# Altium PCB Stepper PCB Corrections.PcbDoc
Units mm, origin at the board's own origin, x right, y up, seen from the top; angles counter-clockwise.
Board outline 195.58 x 105.66 mm, 2 copper layers (Top Layer, Bottom Layer); 57 components, 50 nets, 280 pads, 5 vias.
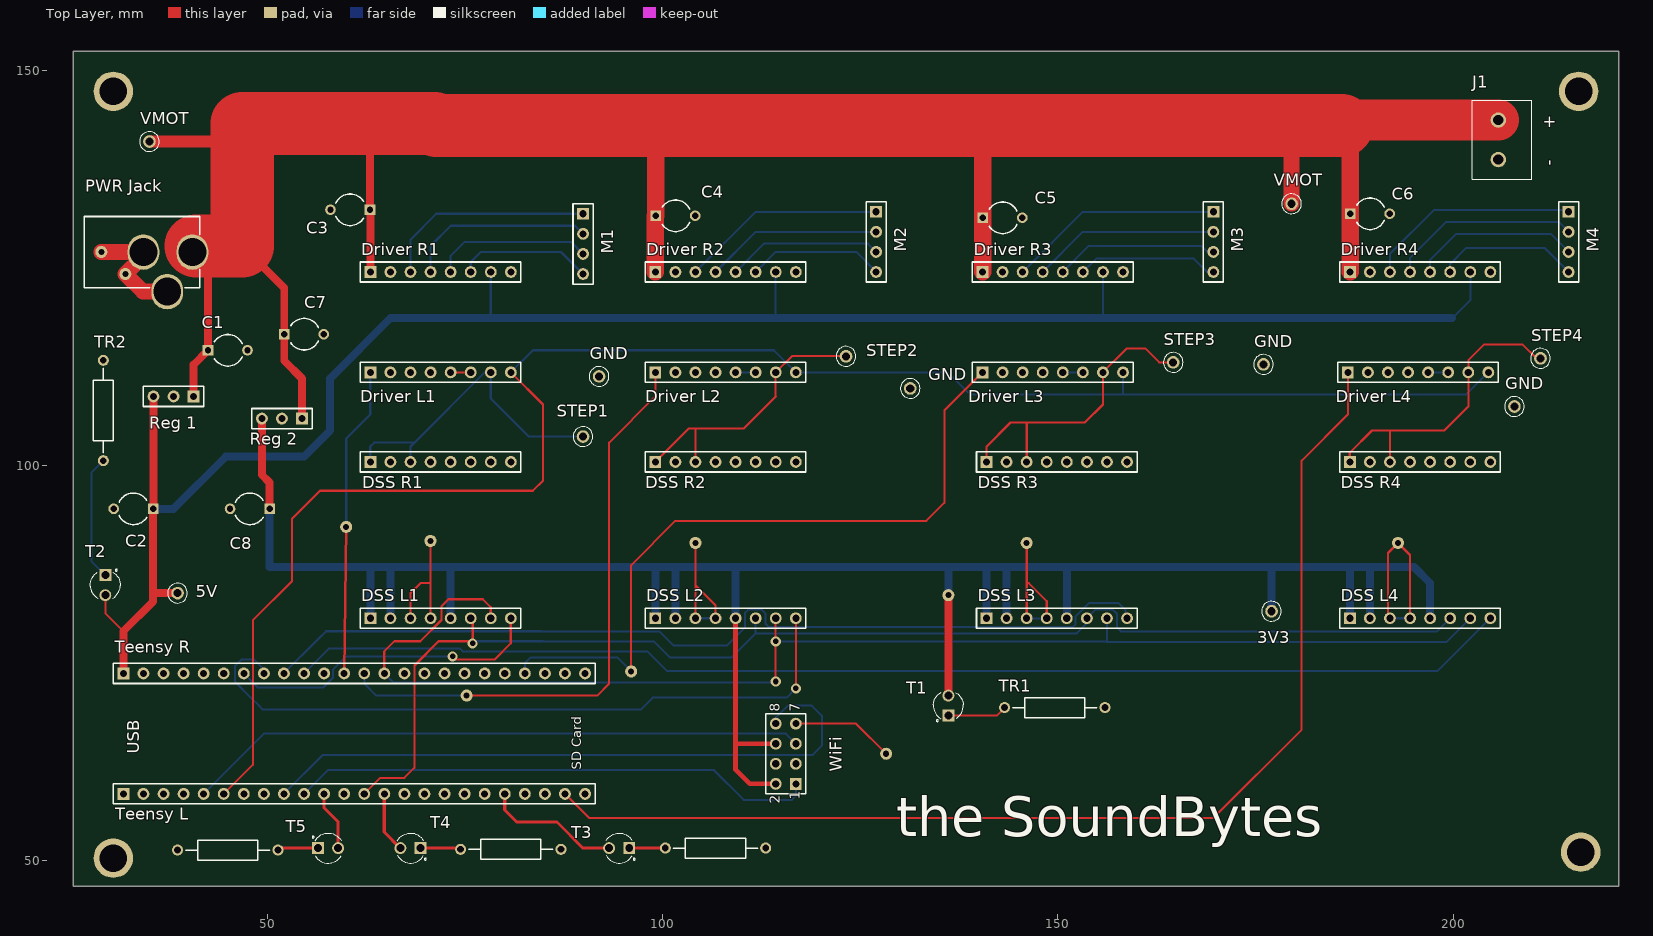
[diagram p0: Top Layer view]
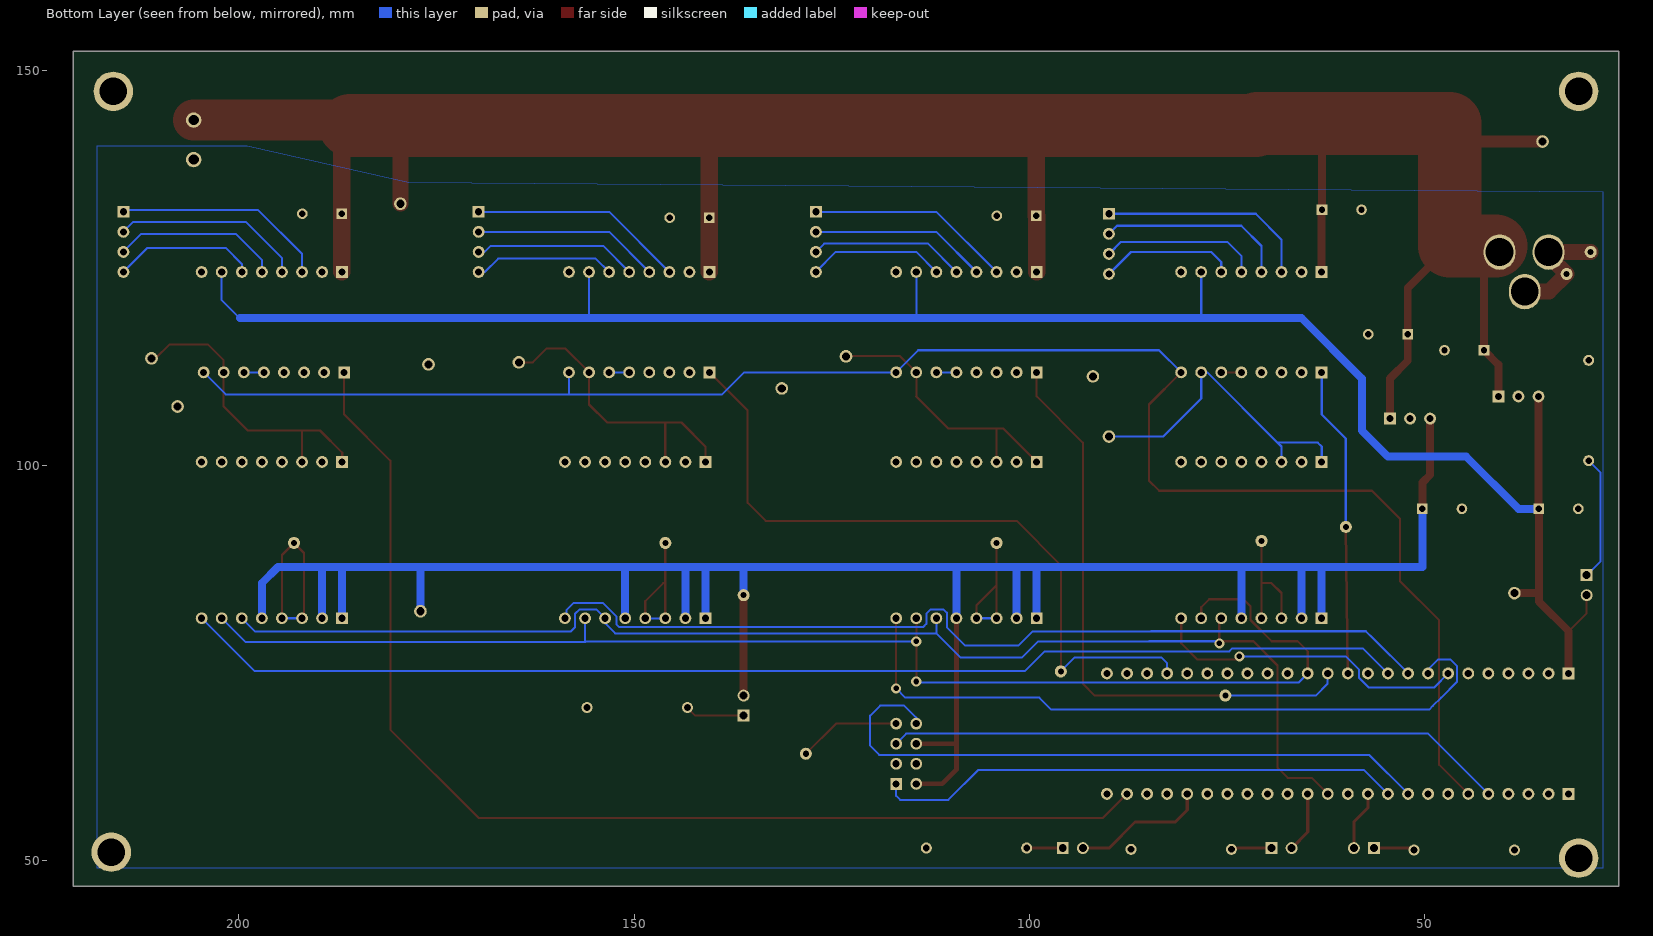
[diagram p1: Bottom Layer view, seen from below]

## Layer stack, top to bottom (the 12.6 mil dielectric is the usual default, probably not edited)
Top Solder: solder mask 0.0102, Solder Resist, Dk 3.5
Top Layer: signal copper 0.0356
Dielectric 1: dielectric 0.32, FR-4, Dk 4.8
Bottom Layer: signal copper 0.0356
Bottom Solder: solder mask 0.0102, Solder Resist, Dk 3.5

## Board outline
25.4,46.736 220.98,46.736 220.98,152.4 25.4,152.4

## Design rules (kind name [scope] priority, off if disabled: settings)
Clearance [All] p1: gap=0.254
PolygonConnect [All] p1: connectstyle=Relief reliefconductorwidth=0.254 reliefentries=4 polygonreliefangle="90 Angle" airgapwidth=0.254
RoutingVias [All] p1: holewidth=0.711 width=1.27 viastyle="Through Hole" minholewidth=0.711 minwidth=1.27 maxholewidth=0.711 maxwidth=1.27
SolderMaskExpansion [All] p1: expansion=0.102
Width Width_1 [All] p1: maxlimit=1 minlimit=0.28 preferedwidth=1 minimp=50.000000 maximp=50.000000 favimp=50.000000
Width [InNet('VMOT')] p2: maxlimit=8.2 minlimit=7.6 preferedwidth=8 minimp=50.000000 maximp=50.000000 favimp=50.000000
30 further rules are at their usual default settings.

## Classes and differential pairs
component class "Stepper Teensy Breakout": 3V3 5V C1 C2 C3 C4 C5 C6 C7 C8 "Driver L1" "Driver L2" "Driver L3" "Driver L4" "Driver R1" "Driver R2" "Driver R3" "Driver R4" "DSS L1" "DSS L2" "DSS L3" "DSS L4" "DSS R1" "DSS R2" "DSS R3" "DSS R4" GND J1 M1 M2 M3 M4 "PWR Jack" "Reg 1" "Reg 2" STEP1 STEP2 STEP3 STEP4 T1 T2 T3 T4 T5 "Teensy L" "Teensy R" TR1 TR2 VMOT WiFi

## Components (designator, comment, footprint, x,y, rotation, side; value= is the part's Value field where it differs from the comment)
3V3 "" TPCW51D250H460P 177.038,81.534 r0 top (schematic designator TP11)
5V "" TPCW51D250H460P 38.608,83.82 r90 top (schematic designator TP10)
C1 "Cap2" CAPR5-4X5 44.958,114.554 r0 top
C2 "Cap2" CAPR5-4X5 33.02,94.488 r180 top
C3 "" CAPR5-4X5 60.452,132.334 r180 top
C4 "Cap2" CAPR5-4X5 101.6,131.572 r0 top
C5 "Cap2" CAPR5-4X5 143.002,131.318 r0 top
C6 "Cap2" CAPR5-4X5 189.484,131.826 r0 top
C7 "Cap2" CAPR5-4X5 54.61,116.586 r0 top
C8 "Cap2" CAPR5-4X5 47.752,94.488 r180 top
"Driver L1" "Header 8" HDR1X8 63,111.76 r0 top
"Driver L2" "Header 8" HDR1X8 99.06,111.76 r0 top locked
"Driver L3" "Header 8" HDR1X8 140.462,111.76 r0 top locked
"Driver L4" "Header 8" HDR1X8 186.69,111.76 r0 top locked
"Driver R1" "Header 8" HDR1X8 63,124.46 r0 top
"Driver R2" "Header 8" HDR1X8 99.06,124.46 r0 top locked
"Driver R3" "Header 8" HDR1X8 140.462,124.46 r0 top locked
"Driver R4" "Header 8" HDR1X8 186.944,124.46 r0 top locked
"DSS L1" "Header 8" HDR1X8 63,80.645 r0 top locked
"DSS L2" "Header 8" HDR1X8 99.06,80.645 r0 top
"DSS L3" "Header 8" HDR1X8 140.97,80.645 r0 top locked
"DSS L4" "Header 8" HDR1X8 186.944,80.645 r0 top
"DSS R1" "Header 8" HDR1X8 63,100.42 r0 top locked
"DSS R2" "Header 8" HDR1X8 99.06,100.42 r0 top
"DSS R3" "Header 8" HDR1X8 140.97,100.42 r0 top
"DSS R4" "Header 8" HDR1X8 186.944,100.42 r0 top
GND "" TPCW51D250H460P 207.772,107.442 r0 top (schematic designator TP8)
GND "" TPCW51D250H460P 91.948,111.252 r0 top (schematic designator TP7)
GND "" TPCW51D250H460P 176.022,112.776 r0 top (schematic designator TP6)
GND "" TPCW51D250H460P 131.318,109.728 r0 top (schematic designator TP5)
J1 "" 691102710002 205.74,141.184 r270 top
M1 "Header 4" HDR1X4 89.916,131.826 r270 top (schematic designator "Motor 1")
M2 "Header 4" HDR1X4 127,132.08 r270 top (schematic designator "Motor 2")
M3 "Header 4" HDR1X4 169.672,132.08 r270 top (schematic designator "Motor 3")
M4 "Header 4" HDR1X4 214.63,132.08 r270 top (schematic designator "Motor 4")
"PWR Jack" "PWR2.5" KLD-0202 26.79,126.984 r0 top
"Reg 1" "Header 3" HDR1X3 40.64,108.712 r180 top (schematic designator "Sw Reg")
"Reg 2" "Header 2" HDR1X3 54.356,105.918 r180 top (schematic designator "Sw Reg1")
STEP1 "" TPCW51D250H460P 89.916,103.632 r0 top (schematic designator TP1)
STEP2 "" TPCW51D250H460P 123.19,113.792 r0 top (schematic designator TP2)
STEP3 "" TPCW51D250H460P 164.592,113.03 r0 top (schematic designator TP3)
STEP4 "" TPCW51D250H460P 211.074,113.538 r0 top (schematic designator TP4)
T1 "LTL-1CHYE" LED_LTL-1CHYE_LTL-1CHYE(Primary) 136.144,69.596 r90 top
T2 "LTL-1CHYE" LED_LTL-1CHYE_LTL-1CHYE(Primary) 29.464,84.836 r270 top
T3 "LTL-1CHYE" LED_LTL-1CHYE_LTL-1CHYE(Primary) 94.488,51.562 r180 top
T4 "LTL-1CHYE" LED_LTL-1CHYE_LTL-1CHYE(Primary) 68.072,51.562 r180 top
T5 "LTL-1CHYE" LED_LTL-1CHYE_LTL-1CHYE(Primary) 57.658,51.562 r0 top
"Teensy L" "Header 24" HDR1X24 31.75,58.42 r0 top locked
"Teensy R" "Header 24" HDR1X24 31.75,73.66 r0 top locked
TR1 "" AXIAL-0.5 149.606,69.342 r180 top
TR2 "" AXIAL-0.5 29.21,106.934 r270 top
TR3 "" AXIAL-0.5 106.68,51.562 r180 top
TR4 "" AXIAL-0.5 80.772,51.402 r180 top
TR5 "" AXIAL-0.5 44.958,51.308 r180 top
VMOT "" TPCW51D250H460P 179.578,133.096 r180 top (schematic designator TP12)
VMOT "" TPCW51D250H460P 35.052,140.97 r0 top (schematic designator TP9)
WiFi "Header 4X2" HDR2X4 116.84,59.69 r90 top (schematic designator ESP)

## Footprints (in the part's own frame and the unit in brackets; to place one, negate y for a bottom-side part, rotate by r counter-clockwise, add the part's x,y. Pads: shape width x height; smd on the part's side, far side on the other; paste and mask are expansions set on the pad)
691102710002 [mm]
  round 1.95 hole 1.3: 1(-2.5,0) 2(2.5,0)
  silkscreen extent -5,-3.3 5,4.2
AXIAL-0.5 [mm] "Axial Device, Thru-Hole; 2 Leads; 0.5 in Pin Spacing"
  round 1.4 hole 0.85: 1(-6.35,0) 2(6.35,0)
  silkscreen extent -5.33,-1.27 5.33,1.27
CAPR5-4X5 [mm] "Capacitor; 2 Leads"
  rect 1.35x1.35 hole 0.8: 1(-2.5,0)
  round 1.35 hole 0.8: 2(2.5,0)
  silkscreen extent -1.69,-2 1.82,2
HDR1X3 [mm] "Connector; Header; 3 Position"
  rect 1.5x1.5 hole 0.9: 1(0,0)
  round 1.5 hole 0.9: 2(2.54,0) 3(5.08,0)
  silkscreen extent -1.27,-1.27 6.35,1.27
HDR1X4 [mm] "Connector; Header; 4 Position"
  rect 1.5x1.5 hole 0.9: 1(0,0)
  round 1.5 hole 0.9: 2(2.54,0) 3(5.08,0) 4(7.62,0)
  silkscreen extent -1.27,-1.27 8.89,1.27
HDR1X8 [mm] "Connector; Header; 8 Position"
  rect 1.5x1.5 hole 0.9: 1(0,0)
  round 1.5 hole 0.9: 2(2.54,0) 3(5.08,0) 4(7.62,0) 5(10.16,0) 6(12.7,0) 7(15.24,0) 8(17.78,0)
  silkscreen extent -1.27,-1.27 19.05,1.27
HDR1X24 [mm] "Connector; Header; 24 Position"
  rect 1.5x1.5 hole 0.9: 1(0,0)
  round 1.5 hole 0.9: 2(2.54,0) 3(5.08,0) 4(7.62,0) 5(10.16,0) 6(12.7,0) 7(15.24,0) 8(17.78,0) 9(20.32,0) 10(22.86,0) 11(25.4,0) 12(27.94,0) 13(30.48,0) 14(33.02,0) 15(35.56,0) 16(38.1,0) 17(40.64,0) 18(43.18,0) 19(45.72,0) 20(48.26,0) 21(50.8,0) 22(53.34,0) 23(55.88,0) 24(58.42,0)
  silkscreen extent -1.27,-1.27 59.69,1.27
HDR2X4 [mm] "Connector; Header; 4x2 Position"
  rect 1.5x1.5 hole 0.9: 1(0,0)
  round 1.5 hole 0.9: 2(0,2.54) 3(2.54,0) 4(2.54,2.54) 5(5.08,0) 6(5.08,2.54) 7(7.62,0) 8(7.62,2.54)
  silkscreen extent -1.27,-1.27 8.89,3.81
KLD-0202 [mm] "DC Power Jack, 2.5mm, KLD Series, PCB Mount"
  oval 4x4.5 hole 3.5: 1(13.7,0) 2(7.5,0) 3(10.5,-5)
  round 1.5 hole 0.2: 1A(13.7,-1.25) 1B(13.7,1.25) 2A(7.5,-1) 2B(7.5,1) 3A(9.5,-5) 3B(11.5,-5)
  silkscreen extent 0,-4.5 14.6,4.5
LED_LTL-1CHYE_LTL-1CHYE(Primary) [mm]
  round 1.508 hole 1: A(1.27,0)
  rect 1.508x1.508 hole 1: C(-1.27,0)
  silkscreen extent -2.03,-1.9 1.66,1.9
TPCW51D250H460P [mm]
  round 1.6 hole 1.02: 1(0,0)
  silkscreen extent -1.25,-1.25 1.25,1.25

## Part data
3V3 5V GND GND GND GND STEP1 STEP2 STEP3 STEP4 VMOT VMOT: library part 5003, "Test Point; Orange; Thru-Hole; Snap-Fit; SilverPlate; 0.040 in. Dia.; 0.300 In."
C1 C2 C4 C5 C6 C7 C8: "Capacitor"
C3: library part Cap2, "Capacitor"
"Driver L1" "Driver L2" "Driver L3" "Driver L4" "Driver R1" "Driver R2" "Driver R3" "Driver R4" "DSS L1" "DSS L2" "DSS L3" "DSS L4" "DSS R1" "DSS R2" "DSS R3" "DSS R4": "Header, 8-Pin"
J1: library part 691102710002, "102 Series 5mm Pitch Straight, PCB Terminal Block, Through Hole, 2 Way"
M1 M2 M3 M4: "Header, 4-Pin"
"PWR Jack": "Low Voltage Power Supply Connector"
"Reg 1": "Header, 3-Pin"
"Reg 2": library part "Header 3", "Header, 3-Pin"
T1 T2 T3 T4 T5: "Yellow 3.1 mm 45° Tinted Clear 40 mcd 2.1 V LED Through Hole"
"Teensy L" "Teensy R": "Header, 24-Pin"
TR1 TR2 TR3 TR4 TR5: library part "Res Semi", "Semiconductor Resistor"
WiFi: "Header, 4-Pin, Dual row"

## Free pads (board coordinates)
  round 5 hole 3.5: 0(30.48,147.32) 6(215.9,147.32) 7(216.154,51.054) 8(30.48,50.292)
  round 1.524 hole 0.762: 2(28.956,127) 3(32.004,124.206) 9(75.184,70.866) 10(96.012,73.914) 11(136.144,83.566) 15(70.612,90.424) 16(104.14,90.17) 17(146.05,90.17) 18(193.04,90.17) 19(128.27,63.5) 20(59.944,92.202)

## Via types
v1: diameter 1.27, hole 0.711, Top Layer to Bottom Layer, 5 vias

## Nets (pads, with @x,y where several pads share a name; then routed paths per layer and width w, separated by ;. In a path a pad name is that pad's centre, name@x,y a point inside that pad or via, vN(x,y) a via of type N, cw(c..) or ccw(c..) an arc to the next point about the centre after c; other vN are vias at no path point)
1A_A: "Driver R1.5" M1.3 | length 20.2
  Bottom Layer w0.28: 73.16,124.46 73.16,126.5 74.93,128.27 88.392,128.27 M1.3
1A_B: "Driver R2.5" M2.3 | length 19.7
  Bottom Layer w0.254: 109.22,124.46 112.801,128.041 125.959,128.041 M2.3
1A_C: "Driver R3.5" M3.3 | length 20.7
  Bottom Layer w0.254: 150.622,124.46 153.924,127.762 168.148,127.762 168.91,127 M3.3
1A_D: "Driver R4.5" M4.3 | length 21.4
  Bottom Layer w0.254: 197.104,124.46 197.104,125.984 200.406,129.286 212.344,129.286 M4.3
1B_A: "Driver R1.6" M1.4 | length 17.2
  Bottom Layer w0.28: 75.7,124.46 75.7,125.738 76.962,127 87.122,127 M1.4
1B_B: "Driver R2.6" M2.4 | length 17.3
  Bottom Layer w0.254: 111.76,124.46 114.3,127 124.46,127 M2.4
1B_C: "Driver R3.6" M3.4 | length 17.9
  Bottom Layer w0.254: 153.162,124.46 154.864,126.162 167.208,126.162 168.91,124.46 M3.4
1B_D: "Driver R4.6" M4.4 | length 18.1
  Bottom Layer w0.254: 199.644,124.46 199.644,125.476 201.676,127.508 211.582,127.508 M4.4
2A_A: "Driver R1.4" M1.2 | length 24.1
  Bottom Layer w0.28: 70.62,124.46 70.62,127.745 73.177,130.302 88.9,130.302 M1.2
2A_B: "Driver R2.4" M2.2 | length 22.4
  Bottom Layer w0.254: 106.68,124.46 111.76,129.54 M2.2
2A_C: "Driver R3.4" M3.2 | length 23.7
  Bottom Layer w0.254: 148.082,124.46 153.162,129.54 M3.2
2A_D: "Driver R4.4" M4.2 | length 24.3
  Bottom Layer w0.254: 194.564,124.46 194.564,126.238 199.136,130.81 213.36,130.81 M4.2
2B_A: "Driver R1.3" M1.1 | length 27.3
  Bottom Layer w0.28: 68.08,124.46 68.08,128.557 71.349,131.826 M1.1
2B_B: "Driver R2.3" M2.1 | length 26
  Bottom Layer w0.254: 104.14,124.46 111.76,132.08 M2.1
2B_C: "Driver R3.3" M3.1 | length 27.3
  Bottom Layer w0.254: 145.542,124.46 153.162,132.08 M3.1
2B_D: "Driver R4.3" M4.1 | length 27.3
  Bottom Layer w0.254: 192.024,124.46 192.024,126.746 197.612,132.334 214.376,132.334 M4.1
3V3: 3V3.1 "DSS L1.1" "DSS L1.2" "DSS L1.5" "DSS L2.1" "DSS L2.2" "DSS L2.5" "DSS L3.1" "DSS L3.2" "DSS L3.5" "DSS L4.1" "DSS L4.2" "DSS L4.5" "Reg 2.3" C8.1 pad.11 T1.A WiFi.2 WiFi.6 | length 294.5
  Top Layer w0.6: 109.22,80.645 109.22,64.77 ; WiFi.2 110.998,59.69 109.22,61.468 109.22,64.77 ; WiFi.6 109.22,64.77
  Top Layer w1: 49.276,105.918 49.276,98.806 50.252,97.83 C8.1 ; T1.A pad.11
  Bottom Layer w1: C8.1 50.252,87.122 63,87.122 ; 63,80.645 63,87.122 ; 65.54,80.645 65.54,87.114 65.532,87.122 ; 73.16,80.645 73.16,87.114 73.152,87.122 ; 99.06,80.645 99.06,87.122 ; 101.6,80.645 101.6,87.122 ; 109.22,80.645 109.22,87.122 ; pad.11 136.144,87.122 ; 140.97,80.645 140.97,87.122 ; 143.51,80.645 143.51,87.122 ; 151.13,80.645 151.13,87.122 ; 3V3.1 177.038,87.122 ; 186.944,80.645 186.944,87.122 ; 189.484,80.645 189.484,87.122 ; 197.104,80.645 197.104,85.09 195.072,87.122 189.484,87.122 ; 63,87.122 65.532,87.122 ; 65.532,87.122 73.152,87.122 ; 73.152,87.122 99.06,87.122 ; 99.06,87.122 101.6,87.122 ; 101.6,87.122 109.22,87.122 ; 109.22,87.122 136.144,87.122 ; 136.144,87.122 140.97,87.122 ; 140.97,87.122 143.51,87.122 ; 143.51,87.122 151.13,87.122 ; 151.13,87.122 177.038,87.122 ; 177.038,87.122 186.944,87.122 ; 186.944,87.122 189.484,87.122
5V: 5V.1 "Driver R1.7" "Driver R2.7" "Driver R3.7" "Driver R4.7" "Reg 1.3" "Teensy R.1" C2.1 T2.A | length 247.8
  Top Layer w0.254: T2.A 29.464,81.28 31.75,78.994
  Top Layer w0.28: C2.1 C2.1@35.56,94.528
  Top Layer w1: 31.75,73.66 31.75,78.994 35.52,82.764 35.52,83.82 ; C2.1 35.52,83.82 ; C2.1@35.56,94.528 35.56,108.712 ; 5V.1 35.52,83.82
  Bottom Layer w0.254: 114.3,118.618 114.3,124.46 ; 155.702,118.618 155.702,124.46 ; 199.898,118.618 202.184,120.904 202.184,124.46
  Bottom Layer w0.28: 78.232,118.618 78.24,118.626 78.24,124.46
  Bottom Layer w1: C2.1 38.1,94.488 44.704,101.092 54.61,101.092 57.912,104.394 57.912,110.998 65.532,118.618 78.232,118.618 114.3,118.618 155.702,118.618 199.898,118.618
24: "Teensy L.14" T4.A | length 7.7
  Top Layer w0.4: 64.77,58.42 64.77,53.594 T4.A
28: "Teensy L.20" T3.A | length 17.2
  Top Layer w0.4: 80.01,58.42 80.01,56.388 81.534,54.864 86.614,54.864 89.916,51.562 T3.A
CS1: "DSS L1.8" "Teensy R.7" | length 40.9
  Top Layer w0.28: v1(73.406,75.819) 73.787,75.438 78.74,75.438 80.78,77.478 80.78,80.645
  Bottom Layer w0.254: 46.99,73.66 48.768,71.882 57.023,71.882 58.293,73.152 58.293,74.168 59.944,75.819 v1(73.406,75.819)
CS2: "DSS L2.8" "Teensy R.8" | length 89.4
  Top Layer w0.254: v1(116.84,71.78) 116.84,80.645
  Bottom Layer w0.254: 49.53,73.66 49.53,74.168 48.26,75.438 46.736,75.438 45.847,74.549 45.847,72.644 47.879,70.612 48.938,69.553 49.403,69.088 97.199,69.088 98.723,70.612 115.672,70.612 v1(116.84,71.78)
CS3: "DSS L3.8" "Teensy R.9" | length 117.4
  Bottom Layer w0.254: 52.07,73.66 56.49,78.08 ; 84.582,78.994 99.568,78.994 101.346,77.216 108.153,77.216 110.439,79.502 110.439,81.356 110.859,81.776 112.458,81.776 113.03,81.204 113.03,79.934 113.45,79.514 151.892,79.514 152.261,79.883 152.261,80.887 153.924,82.55 157.702,82.55 158.535,81.717 158.535,80.86 158.75,80.645
  Bottom Layer w0.28: 56.49,78.08 57.404,78.994 84.582,78.994
CS4: "DSS L4.8" "Teensy R.10" | length 155.4
  Bottom Layer w0.254: 54.61,73.66 57.785,76.835 74.295,76.835 74.676,76.454 98.044,76.454 100.559,73.939 198.018,73.939 204.724,80.645
DIR: "Driver L1.8" "Driver L2.8" "Driver L3.8" "Driver L4.8" "Teensy L.6" | length 218.6
  Top Layer w0.254: 44.45,58.42 48.133,62.103 48.133,80.391 53.086,85.344
  Top Layer w0.28: 53.086,85.344 53.086,93.218 56.642,96.774 83.566,96.774 84.836,98.044 84.836,107.704 80.78,111.76
  Bottom Layer w0.254: 114.046,114.554 116.84,111.76 136.068,111.76 138.862,108.966 158.242,108.966 ; 158.242,111.76 158.242,108.966 ; 204.47,111.76 201.676,108.966 158.242,108.966
  Bottom Layer w0.28: 80.78,111.76 83.574,114.554 114.046,114.554
ENA1: "Driver L1.1" "Teensy R.12" pad.20 | length 39.4
  Top Layer w0.28: 59.69,73.66 pad.20
  Bottom Layer w0.28: pad.20 59.944,103.378 63,106.434 63,111.76
ENA2: "Driver L2.1" "Teensy R.13" pad.9 | length 75.3
  Top Layer w0.254: pad.9 91.694,70.866 93.218,72.39 93.218,102.87 99.06,108.712 99.06,111.76
  Bottom Layer w0.254: 62.23,73.66 62.23,72.39 63.754,70.866 pad.9
ENA3: "Driver L3.1" "Teensy R.21" pad.10 | length 90.6
  Top Layer w0.254: pad.10 96.012,87.376 101.6,92.964 133.35,92.964 135.636,95.25 135.636,106.934 140.462,111.76
  Bottom Layer w0.254: 82.55,73.66 82.55,74.93 83.312,75.692 94.234,75.692 pad.10
ENA4: "Driver L4.1" "Teensy L.23" | length 146.7
  Top Layer w0.254: 87.63,58.42 90.678,55.372 169.672,55.372 180.848,66.548 180.848,100.584 186.69,106.426 186.69,111.76
GND: "Driver R1.2" "Driver R1.8" "Driver R2.2" "Driver R2.8" "Driver R3.2" "Driver R3.8" "Driver R4.2" "Driver R4.8" "DSS L1.3" "DSS L1.4" "DSS L2.3" "DSS L2.4" "DSS L3.3" "DSS L3.4" "DSS L4.3" "DSS L4.4" "PWR Jack.2" "PWR Jack.2A" "PWR Jack.2B" "PWR Jack.3" "PWR Jack.3A" "PWR Jack.3B" "Reg 1.2" "Reg 2.2" "Teensy L.1" "Teensy R.2" "Teensy R.15" C1.2 C2.2 C3.2 C4.2 C5.2 C6.2 C7.2 C8.2 GND.1 J1.2 pad.2 pad.3 pad.15 pad.16 pad.17 pad.18 pad.19 TR1.1 TR2.1 TR3.1 TR4.1 TR5.2 WiFi.7 | length 102.9
  Top Layer w0.28: 68.08,80.645 68.08,83.828 69.342,85.09 70.612,85.09 ; pad.15 70.612,85.09 ; 70.62,80.645 70.612,80.653 70.612,85.09 ; 104.14,80.518 104.14,80.645 104.14,84.836 ; pad.16 104.14,84.836 ; 106.68,80.645 106.68,82.296 104.14,84.836 ; WiFi.7 124.46,67.31 pad.19 ; 146.05,80.645 146.05,85.09 ; pad.17 146.05,85.09 ; 148.59,80.645 148.59,82.804 146.304,85.09 146.05,85.09 ; 192.024,80.645 191.77,80.899 191.77,88.9 pad.18 194.564,88.646 194.564,80.645
  Top Layer w2: pad.2 33.274,127 33.29,126.984 ; 34.29,125.984 34.036,126.238 ; 34.29,127.984 34.29,126.984 34.29,126.492 34.036,126.238 ; 37.29,121.984 36.29,121.984 34.226,121.984 pad.3 34.036,126.238
  Bottom Layer w0.254: 146.05,80.645 148.59,80.645 ; 189.484,124.46 189.484,124.714
  Bottom Layer w0.28: 104.14,80.645 106.68,80.645 ; 192.024,80.645 194.564,80.645
NetT1_C: T1.C TR1.2 | length 7.5
  Top Layer w0.254: T1.C 142.24,68.326 TR1.2
NetT2_C: T2.C TR2.2 | length 15.8
  Bottom Layer w0.254: TR2.2 27.686,99.06 27.686,87.884 T2.C
NetT3_C: T3.C TR3.2 | length 4.6
  Top Layer w0.4: T3.C TR3.2
NetT4_C: T4.C TR4.2 | length 5.1
  Top Layer w0.4: T4.C 74.262,51.562 TR4.2
NetT5_A: "Teensy L.11" T5.A | length 7.6
  Top Layer w0.4: 57.15,58.42 57.15,56.642 58.928,54.864 T5.A
NetT5_C: T5.C TR5.1 | length 5.2
  Top Layer w0.4: TR5.1 51.562,51.562 T5.C
PIN3: "Teensy L.5" WiFi.5 | length 78.6
  Bottom Layer w0.254: 41.91,58.42 49.53,66.04 115.57,66.04 WiFi.5
PIN7: "Teensy L.9" WiFi.8 | length 82.2
  Bottom Layer w0.254: 52.07,58.42 57.011,63.361 118.987,63.361 120.142,64.516 120.142,68.326 118.872,69.596 115.824,69.596 114.3,68.072 WiFi.8
PIN8: "Teensy L.10" WiFi.1 | length 66.8
  Bottom Layer w0.254: 54.61,58.42 57.658,61.468 106.426,61.468 110.236,57.658 116.332,57.658 116.84,58.166 WiFi.1
RESET1: "Driver L1.5" "Driver L1.6" | length 2.5
  Top Layer w0.28: 73.16,111.76 75.7,111.76
RESET2: "Driver L2.5" "Driver L2.6" | length 2.5
  Bottom Layer w0.254: 109.22,111.76 111.76,111.76
RESET3: "Driver L3.5" "Driver L3.6" | length 2.5
  Bottom Layer w0.254: 150.622,111.76 153.162,111.76
RESET4: "Driver L4.5" "Driver L4.6" | length 2.5
  Bottom Layer w0.254: 196.85,111.76 199.39,111.76
SCK: "DSS L1.7" "DSS L2.7" "DSS L3.7" "DSS L4.7" "Teensy R.14" | length 172.4
  Top Layer w0.254: v1(114.3,72.644) v1(114.3,77.724) 114.3,80.645
  Top Layer w0.28: 64.77,73.66 64.77,76.454 66.04,77.724 69.317,77.724 72.016,80.423 72.016,82.176 72.898,83.058 77.216,83.058 78.24,82.034 78.24,80.645
  Bottom Layer w0.254: 64.77,73.66 65.913,72.517 v1@114.173,72.517 ; v1@114.046,72.39 v1@114.173,72.517 ; v1(114.3,72.644) v1@114.173,72.517 ; v1(114.3,77.724) 156.108,77.724 156.21,77.622 ; 156.21,80.645 156.21,77.622 ; 202.184,80.645 199.161,77.622 156.21,77.622
  Bottom Layer w0.28: 78.24,80.645 78.359,80.645
SDA: "DSS L1.6" "DSS L2.6" "DSS L3.6" "DSS L4.6" "Teensy L.13" | length 165.1
  Top Layer w0.254: 62.23,58.42 64.262,60.452 67.31,60.452 68.58,61.722 68.58,74.676
  Top Layer w0.28: 68.58,74.676 71.628,77.724 75.438,77.724 75.692,77.47 v1(75.946,77.47) 75.946,80.383 75.692,80.637 75.7,80.645
  Bottom Layer w0.254: 84.836,77.724 98.869,77.724 100.901,75.692 108.712,75.692 111.76,78.74 ; 111.76,80.645 111.76,78.74 ; 199.644,80.645 197.993,78.994 157.988,78.994 157.48,79.502 157.48,81.204 156.908,81.776 154.801,81.776 153.67,80.645 153.67,80.01 152.4,78.74 111.76,78.74
  Bottom Layer w0.28: v1(75.946,77.47) 75.946,77.724 84.836,77.724
STEP1: "Driver L1.7" "DSS R1.1" "DSS R1.3" STEP1.1 | length 40.7
  Bottom Layer w0.28: 63,100.42 63,102.37 63.5,102.87 68.58,102.87 ; 68.08,100.42 68.08,102.37 68.58,102.87 ; STEP1.1 83.058,103.632 78.24,108.45 78.24,111.76 77.47,111.76 68.58,102.87
STEP2: "Driver L2.7" "DSS R2.1" "DSS R2.3" STEP2.1 | length 35.2
  Top Layer w0.254: 114.3,108.712 114.3,111.76 116.357,113.817 STEP2.1@122.682,113.817
  Top Layer w0.28: 99.06,100.42 103.288,104.648 104.14,104.648 ; 104.14,100.42 104.14,104.648 ; 114.3,108.712 110.236,104.648 104.14,104.648
STEP3: "Driver L3.7" "DSS R3.1" "DSS R3.3" STEP3.1 | length 38.8
  Top Layer w0.254: 155.702,107.696 155.702,111.76 158.75,114.808 161.036,114.808 162.814,113.03 STEP3.1
  Top Layer w0.28: 140.97,100.42 140.97,102.362 144.018,105.41 146.05,105.41 ; 146.05,100.42 146.05,105.41 ; 155.702,107.696 153.416,105.41 146.05,105.41
STEP4: "Driver L4.7" "DSS R4.1" "DSS R4.3" STEP4.1 | length 39.1
  Top Layer w0.254: 201.93,107.442 201.93,111.76 201.93,113.284 203.962,115.316 208.788,115.316 210.566,113.538 STEP4.1
  Top Layer w0.28: 186.944,100.42 186.944,101.6 189.738,104.394 192.024,104.394 ; 192.024,100.42 192.024,104.394 ; 201.93,107.442 198.882,104.394 192.024,104.394
VMOT: "Driver R1.1" "Driver R2.1" "Driver R3.1" "Driver R4.1" "PWR Jack.1" "PWR Jack.1A" "PWR Jack.1B" "Reg 1.1" "Reg 2.1" C1.1 C3.1 C4.1 C5.1 C6.1 C7.1 J1.1 VMOT.1 | length 321.3
  Top Layer w0.254: 71.108,143.268 71.374,143.002 ; C4.1@99.06,131.532 C4.1 ; 99.06,143.002 99.1,142.962 ; 140.462,124.46 140.502,124.5 ; 140.462,143.002 140.502,142.962 ; 186.944,124.46 186.984,124.5
  Top Layer w0.28: 40.962,127.762 42.458,126.266 ; 185.928,143.002 186.61,143.684
  Top Layer w1: 40.64,108.712 40.64,112.736 C1.1 42.458,126.266 ; 46.793,127.762 52.11,122.445 C7.1 52.11,113.244 54.356,110.998 54.356,105.918 ; 63,124.46 63,132.286 C3.1 62.952,142.974 63.246,143.268
  Top Layer w1.5: VMOT.1@35.052,140.97 46.736,140.97
  Top Layer w2: VMOT.1@179.578,133.096 179.578,143.002
  Top Layer w2.2: 99.06,124.46 C4.1@99.06,131.532 ; C4.1 99.1,142.962 ; 140.502,124.5 C5.1 140.502,142.962 ; 186.984,124.5 C6.1 186.984,141.946
  Top Layer w5.2: 186.61,143.684 J1.1
  Top Layer w8: 40.962,127.762 46.793,127.762 46.793,143.268 63.246,143.268 71.108,143.268 ; 71.374,143.002 99.06,143.002 140.462,143.002 179.578,143.002 185.928,143.002
pads on no net: "Driver L1.2" "Driver L1.3" "Driver L1.4" "Driver L2.2" "Driver L2.3" "Driver L2.4" "Driver L3.2" "Driver L3.3" "Driver L3.4" "Driver L4.2" "Driver L4.3" "Driver L4.4" "DSS R1.2" "DSS R1.4" "DSS R1.5" "DSS R1.6" "DSS R1.7" "DSS R1.8" "DSS R2.2" "DSS R2.4" "DSS R2.5" "DSS R2.6" "DSS R2.7" "DSS R2.8" "DSS R3.2" "DSS R3.4" "DSS R3.5" "DSS R3.6" "DSS R3.7" "DSS R3.8" "DSS R4.2" "DSS R4.4" "DSS R4.5" "DSS R4.6" "DSS R4.7" "DSS R4.8" "Teensy L.2" "Teensy L.3" "Teensy L.4" "Teensy L.7" "Teensy L.8" "Teensy L.12" "Teensy L.15" "Teensy L.16" "Teensy L.17" "Teensy L.18" "Teensy L.19" "Teensy L.21" "Teensy L.22" "Teensy L.24" "Teensy R.3" "Teensy R.4" "Teensy R.5" "Teensy R.6" "Teensy R.11" "Teensy R.16" "Teensy R.17" "Teensy R.18" "Teensy R.19" "Teensy R.20" "Teensy R.22" "Teensy R.23" "Teensy R.24" WiFi.3 WiFi.4

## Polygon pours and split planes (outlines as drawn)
GND on Bottom Layer "GND" (solid, shelved, pour order 0): 27.432,134.633 27.432,49.022 217.932,49.022 217.932,140.462 198.987,140.462 178.506,135.821

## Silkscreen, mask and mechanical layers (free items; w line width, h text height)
Top Overlay:
  text "+" at 211.328,142.748 h1.52
  text "-" at 212.852,137.922 h1.52 r90
  text "USB" at 33.782,63.5 h1.52 r90
  text "SD Card" at 89.662,61.468 h1.2 r90
  text "the SoundBytes" at 129.54,53.086 h5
